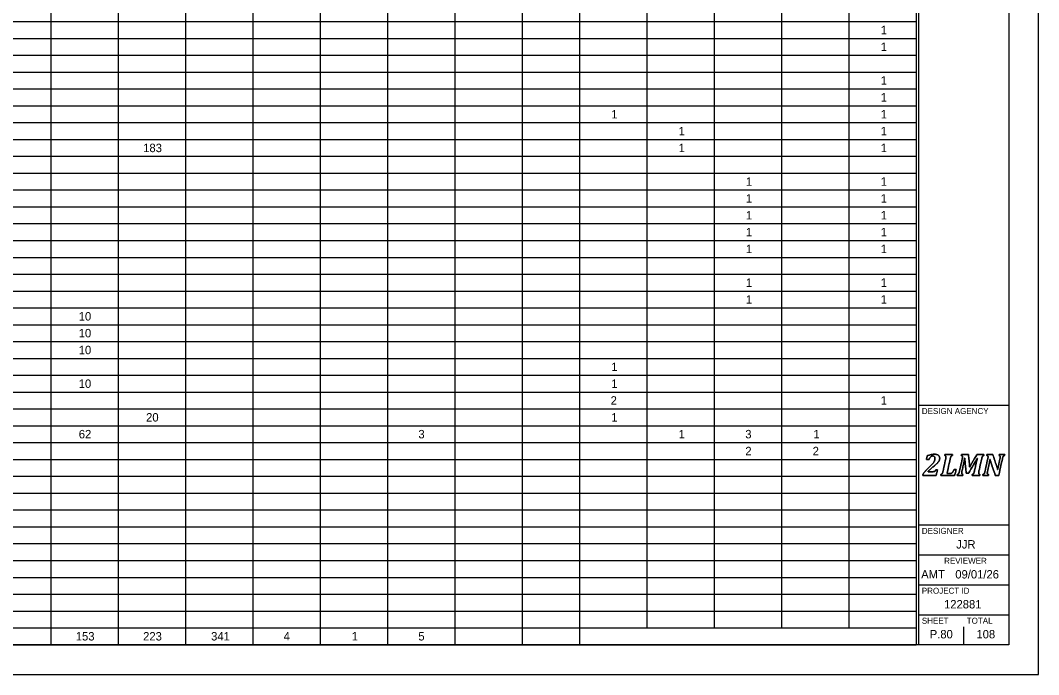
# Model space of a CAD drawing. Extents: x 0 to 34, y 0 to 22.
# Drawn here: x 17 to 34, y 0 to 10.92 of the extents above; entities that cross this region are included whole.
import ezdxf

# ---------------------------------------------------------------- set-up
doc = ezdxf.new("R2010")
doc.units = 0
for name, color, linetype in [('SH_Border', 7, 'Continuous'), ('SH_Cut_Line', 7, 'Continuous'), ('SH_Data', 7, 'Continuous'), ('SH_Text', 7, 'Continuous')]:
    doc.layers.add(name, color=color, linetype=linetype)

msp = doc.modelspace()

# ---------------------------------------------------------------- linework, layer by layer
at = {"layer": 'SH_Border'}
for p, q in [((32, 0.5), (32, 21.5)), ((32, 4.5), (33.5, 4.5)), ((32, 2.5), (33.5, 2.5)), ((32, 2), (33.5, 2)), ((32, 1.5), (33.5, 1.5)), ((32, 1), (33.5, 1))]:
    msp.add_line(p, q, dxfattribs=at)
msp.add_lwpolyline([(1.5, 21.5), (33.5, 21.5), (33.5, 0.5), (1.5, 0.5)], close=True, dxfattribs=at)
at = {"layer": 'SH_Cut_Line'}
msp.add_lwpolyline([(0, 0), (34, 0), (34, 22), (0, 22)], close=True, dxfattribs=at)
at = {"layer": 'SH_Data'}
for p, q in [((32.75, 3.5), (32.75, 3.5)), ((32.75, 0.5), (32.75, 0.8)), ((32.375, 0.675), (32.375, 0.675))]:
    msp.add_line(p, q, dxfattribs=at)
for points in [[(32.237, 3.388), (32.246, 3.388), (32.253, 3.389), (32.258, 3.39), (32.263, 3.392), (32.267, 3.394), (32.27, 3.397), (32.273, 3.401), (32.277, 3.408), (32.281, 3.417), (32.281, 3.417), (32.312, 3.417), (32.312, 3.417), (32.312, 3.417), (32.29, 3.326), (32.29, 3.326), (32.29, 3.326), (32.066, 3.326), (32.066, 3.326), (32.066, 3.326), (32.069, 3.343), (32.069, 3.343), (32.078, 3.358), (32.091, 3.375), (32.106, 3.394), (32.122, 3.412), (32.144, 3.435), (32.172, 3.462), (32.197, 3.486), (32.217, 3.506), (32.23, 3.521), (32.243, 3.537), (32.253, 3.551), (32.259, 3.566), (32.266, 3.58), (32.269, 3.595), (32.269, 3.61), (32.269, 3.622), (32.266, 3.632), (32.26, 3.64), (32.253, 3.647), (32.245, 3.65), (32.234, 3.65), (32.22, 3.65), (32.208, 3.646), (32.198, 3.636), (32.188, 3.627), (32.18, 3.613), (32.172, 3.593), (32.172, 3.593), (32.126, 3.593), (32.126, 3.593), (32.126, 3.593), (32.14, 3.654), (32.14, 3.654), (32.166, 3.663), (32.188, 3.669), (32.205, 3.673), (32.223, 3.676), (32.24, 3.678), (32.258, 3.678), (32.278, 3.678), (32.295, 3.675), (32.309, 3.669), (32.322, 3.664), (32.332, 3.656), (32.339, 3.646), (32.345, 3.637), (32.348, 3.626), (32.348, 3.613), (32.348, 3.602), (32.346, 3.591), (32.342, 3.581), (32.339, 3.571), (32.333, 3.56), (32.324, 3.549), (32.315, 3.539), (32.304, 3.526), (32.289, 3.513), (32.275, 3.499), (32.254, 3.482), (32.228, 3.46), (32.216, 3.45), (32.202, 3.438), (32.188, 3.425), (32.174, 3.412), (32.162, 3.4), (32.154, 3.391), (32.154, 3.391), (32.153, 3.388), (32.153, 3.388), (32.153, 3.388), (32.237, 3.388), (32.237, 3.388)], [(32.237, 3.388), (32.237, 3.388), (32.153, 3.388), (32.153, 3.388), (32.153, 3.388), (32.154, 3.391), (32.154, 3.391), (32.162, 3.4), (32.174, 3.412), (32.188, 3.425), (32.202, 3.438), (32.216, 3.45), (32.228, 3.46), (32.254, 3.482), (32.275, 3.499), (32.289, 3.513), (32.304, 3.526), (32.315, 3.539), (32.324, 3.549), (32.333, 3.56), (32.339, 3.571), (32.342, 3.581), (32.346, 3.591), (32.348, 3.602), (32.348, 3.613), (32.348, 3.626), (32.345, 3.637), (32.339, 3.646), (32.332, 3.656), (32.322, 3.664), (32.309, 3.669), (32.295, 3.675), (32.278, 3.678), (32.258, 3.678), (32.24, 3.678), (32.223, 3.676), (32.205, 3.673), (32.188, 3.669), (32.166, 3.663), (32.14, 3.654), (32.14, 3.654), (32.126, 3.593), (32.126, 3.593), (32.126, 3.593), (32.172, 3.593), (32.172, 3.593), (32.18, 3.613), (32.188, 3.627), (32.198, 3.636), (32.208, 3.646), (32.22, 3.65), (32.234, 3.65), (32.245, 3.65), (32.253, 3.647), (32.26, 3.64), (32.266, 3.632), (32.269, 3.622), (32.269, 3.61), (32.269, 3.595), (32.266, 3.58), (32.259, 3.566), (32.253, 3.551), (32.243, 3.537), (32.23, 3.521), (32.217, 3.506), (32.197, 3.486), (32.172, 3.462), (32.144, 3.435), (32.122, 3.412), (32.106, 3.394), (32.091, 3.375), (32.078, 3.358), (32.069, 3.343), (32.069, 3.343), (32.066, 3.326), (32.066, 3.326), (32.066, 3.326), (32.29, 3.326), (32.29, 3.326), (32.29, 3.326), (32.312, 3.417), (32.312, 3.417), (32.312, 3.417), (32.281, 3.417), (32.281, 3.417), (32.277, 3.408), (32.273, 3.401), (32.27, 3.397), (32.267, 3.394), (32.263, 3.392), (32.258, 3.39), (32.253, 3.389), (32.246, 3.388), (32.237, 3.388)], [(32.518, 3.356), (32.527, 3.356), (32.533, 3.357), (32.538, 3.358), (32.542, 3.36), (32.546, 3.362), (32.55, 3.365), (32.554, 3.368), (32.558, 3.372), (32.562, 3.377), (32.567, 3.382), (32.571, 3.388), (32.576, 3.397), (32.58, 3.405), (32.585, 3.415), (32.589, 3.427), (32.589, 3.427), (32.624, 3.427), (32.624, 3.427), (32.624, 3.427), (32.598, 3.326), (32.598, 3.326), (32.598, 3.326), (32.365, 3.326), (32.365, 3.326), (32.365, 3.326), (32.369, 3.343), (32.369, 3.343), (32.376, 3.345), (32.381, 3.348), (32.385, 3.351), (32.389, 3.355), (32.392, 3.36), (32.395, 3.366), (32.398, 3.373), (32.4, 3.382), (32.403, 3.395), (32.403, 3.395), (32.449, 3.605), (32.449, 3.605), (32.452, 3.615), (32.453, 3.625), (32.453, 3.635), (32.453, 3.642), (32.451, 3.647), (32.448, 3.651), (32.444, 3.654), (32.439, 3.656), (32.432, 3.657), (32.432, 3.657), (32.435, 3.674), (32.435, 3.674), (32.435, 3.674), (32.563, 3.674), (32.563, 3.674), (32.563, 3.674), (32.559, 3.657), (32.559, 3.657), (32.552, 3.655), (32.547, 3.652), (32.543, 3.649), (32.539, 3.645), (32.536, 3.64), (32.533, 3.634), (32.531, 3.627), (32.528, 3.618), (32.525, 3.605), (32.525, 3.605), (32.47, 3.356), (32.47, 3.356), (32.47, 3.356), (32.518, 3.356), (32.518, 3.356)], [(32.518, 3.356), (32.518, 3.356), (32.47, 3.356), (32.47, 3.356), (32.47, 3.356), (32.525, 3.605), (32.525, 3.605), (32.528, 3.618), (32.531, 3.627), (32.533, 3.634), (32.536, 3.64), (32.539, 3.645), (32.543, 3.649), (32.547, 3.652), (32.552, 3.655), (32.559, 3.657), (32.559, 3.657), (32.563, 3.674), (32.563, 3.674), (32.563, 3.674), (32.435, 3.674), (32.435, 3.674), (32.435, 3.674), (32.432, 3.657), (32.432, 3.657), (32.439, 3.656), (32.444, 3.654), (32.448, 3.651), (32.451, 3.647), (32.453, 3.642), (32.453, 3.635), (32.453, 3.625), (32.452, 3.615), (32.449, 3.605), (32.449, 3.605), (32.403, 3.395), (32.403, 3.395), (32.4, 3.382), (32.398, 3.373), (32.395, 3.366), (32.392, 3.36), (32.389, 3.355), (32.385, 3.351), (32.381, 3.348), (32.376, 3.345), (32.369, 3.343), (32.369, 3.343), (32.365, 3.326), (32.365, 3.326), (32.365, 3.326), (32.598, 3.326), (32.598, 3.326), (32.598, 3.326), (32.624, 3.427), (32.624, 3.427), (32.624, 3.427), (32.589, 3.427), (32.589, 3.427), (32.585, 3.415), (32.58, 3.405), (32.576, 3.397), (32.571, 3.388), (32.567, 3.382), (32.562, 3.377), (32.558, 3.372), (32.554, 3.368), (32.55, 3.365), (32.546, 3.362), (32.542, 3.36), (32.538, 3.358), (32.533, 3.357), (32.527, 3.356), (32.518, 3.356)], [(32.829, 3.674), (32.829, 3.674), (32.849, 3.461), (32.849, 3.461), (32.849, 3.461), (32.969, 3.674), (32.969, 3.674), (32.969, 3.674), (33.087, 3.674), (33.087, 3.674), (33.087, 3.674), (33.084, 3.657), (33.084, 3.657), (33.077, 3.655), (33.071, 3.652), (33.067, 3.649), (33.064, 3.645), (33.06, 3.64), (33.058, 3.634), (33.055, 3.627), (33.052, 3.618), (33.05, 3.605), (33.05, 3.605), (33.003, 3.395), (33.003, 3.395), (33.002, 3.39), (33.002, 3.387), (33.001, 3.384), (33.001, 3.382), (33.001, 3.379), (33, 3.376), (33, 3.373), (33, 3.369), (33, 3.365), (33, 3.358), (33.002, 3.353), (33.005, 3.349), (33.008, 3.346), (33.014, 3.344), (33.021, 3.343), (33.021, 3.343), (33.018, 3.326), (33.018, 3.326), (33.018, 3.326), (32.89, 3.326), (32.89, 3.326), (32.89, 3.326), (32.893, 3.343), (32.893, 3.343), (32.9, 3.345), (32.906, 3.348), (32.91, 3.351), (32.914, 3.355), (32.917, 3.36), (32.919, 3.366), (32.922, 3.373), (32.925, 3.382), (32.928, 3.395), (32.928, 3.395), (32.951, 3.502), (32.951, 3.502), (32.954, 3.513), (32.957, 3.529), (32.962, 3.548), (32.967, 3.568), (32.972, 3.588), (32.978, 3.609), (32.978, 3.609), (32.973, 3.609), (32.973, 3.609), (32.965, 3.594), (32.957, 3.579), (32.948, 3.563), (32.948, 3.563), (32.833, 3.364), (32.833, 3.364), (32.833, 3.364), (32.792, 3.364), (32.792, 3.364), (32.792, 3.364), (32.775, 3.518), (32.775, 3.518), (32.773, 3.537), (32.772, 3.554), (32.77, 3.569), (32.769, 3.583), (32.768, 3.597), (32.768, 3.611), (32.768, 3.611), (32.764, 3.611), (32.764, 3.611), (32.761, 3.596), (32.758, 3.578), (32.755, 3.558), (32.751, 3.538), (32.747, 3.521), (32.744, 3.507), (32.744, 3.507), (32.72, 3.395), (32.72, 3.395), (32.719, 3.39), (32.718, 3.387), (32.718, 3.384), (32.717, 3.382), (32.717, 3.379), (32.717, 3.376), (32.717, 3.373), (32.716, 3.369), (32.716, 3.365), (32.716, 3.358), (32.718, 3.353), (32.721, 3.349), (32.725, 3.346), (32.73, 3.344), (32.738, 3.343), (32.738, 3.343), (32.734, 3.326), (32.734, 3.326), (32.734, 3.326), (32.641, 3.326), (32.641, 3.326), (32.641, 3.326), (32.644, 3.343), (32.644, 3.343), (32.651, 3.345), (32.657, 3.348), (32.661, 3.351), (32.665, 3.355), (32.668, 3.36), (32.67, 3.366), (32.673, 3.373), (32.676, 3.382), (32.679, 3.395), (32.679, 3.395), (32.725, 3.605), (32.725, 3.605), (32.727, 3.615), (32.728, 3.625), (32.728, 3.635), (32.728, 3.642), (32.727, 3.647), (32.723, 3.651), (32.72, 3.654), (32.715, 3.656), (32.707, 3.657), (32.707, 3.657), (32.711, 3.674), (32.711, 3.674), (32.711, 3.674), (32.829, 3.674), (32.829, 3.674)], [(32.829, 3.674), (32.829, 3.674), (32.711, 3.674), (32.711, 3.674), (32.711, 3.674), (32.707, 3.657), (32.707, 3.657), (32.715, 3.656), (32.72, 3.654), (32.723, 3.651), (32.727, 3.647), (32.728, 3.642), (32.728, 3.635), (32.728, 3.625), (32.727, 3.615), (32.725, 3.605), (32.725, 3.605), (32.679, 3.395), (32.679, 3.395), (32.676, 3.382), (32.673, 3.373), (32.67, 3.366), (32.668, 3.36), (32.665, 3.355), (32.661, 3.351), (32.657, 3.348), (32.651, 3.345), (32.644, 3.343), (32.644, 3.343), (32.641, 3.326), (32.641, 3.326), (32.641, 3.326), (32.734, 3.326), (32.734, 3.326), (32.734, 3.326), (32.738, 3.343), (32.738, 3.343), (32.73, 3.344), (32.725, 3.346), (32.721, 3.349), (32.718, 3.353), (32.716, 3.358), (32.716, 3.365), (32.716, 3.369), (32.717, 3.373), (32.717, 3.376), (32.717, 3.379), (32.717, 3.382), (32.718, 3.384), (32.718, 3.387), (32.719, 3.39), (32.72, 3.395), (32.72, 3.395), (32.744, 3.507), (32.744, 3.507), (32.747, 3.521), (32.751, 3.538), (32.755, 3.558), (32.758, 3.578), (32.761, 3.596), (32.764, 3.611), (32.764, 3.611), (32.768, 3.611), (32.768, 3.611), (32.768, 3.597), (32.769, 3.583), (32.77, 3.569), (32.772, 3.554), (32.773, 3.537), (32.775, 3.518), (32.775, 3.518), (32.792, 3.364), (32.792, 3.364), (32.792, 3.364), (32.833, 3.364), (32.833, 3.364), (32.833, 3.364), (32.948, 3.563), (32.948, 3.563), (32.957, 3.579), (32.965, 3.594), (32.973, 3.609), (32.973, 3.609), (32.978, 3.609), (32.978, 3.609), (32.972, 3.588), (32.967, 3.568), (32.962, 3.548), (32.957, 3.529), (32.954, 3.513), (32.951, 3.502), (32.951, 3.502), (32.928, 3.395), (32.928, 3.395), (32.925, 3.382), (32.922, 3.373), (32.919, 3.366), (32.917, 3.36), (32.914, 3.355), (32.91, 3.351), (32.906, 3.348), (32.9, 3.345), (32.893, 3.343), (32.893, 3.343), (32.89, 3.326), (32.89, 3.326), (32.89, 3.326), (33.018, 3.326), (33.018, 3.326), (33.018, 3.326), (33.021, 3.343), (33.021, 3.343), (33.014, 3.344), (33.008, 3.346), (33.005, 3.349), (33.002, 3.353), (33, 3.358), (33, 3.365), (33, 3.369), (33, 3.373), (33, 3.376), (33.001, 3.379), (33.001, 3.382), (33.001, 3.384), (33.002, 3.387), (33.002, 3.39), (33.003, 3.395), (33.003, 3.395), (33.05, 3.605), (33.05, 3.605), (33.052, 3.618), (33.055, 3.627), (33.058, 3.634), (33.06, 3.64), (33.064, 3.645), (33.067, 3.649), (33.071, 3.652), (33.077, 3.655), (33.084, 3.657), (33.084, 3.657), (33.087, 3.674), (33.087, 3.674), (33.087, 3.674), (32.969, 3.674), (32.969, 3.674), (32.969, 3.674), (32.849, 3.461), (32.849, 3.461), (32.849, 3.461), (32.829, 3.674), (32.829, 3.674)], [(33.137, 3.674), (33.137, 3.674), (33.234, 3.674), (33.234, 3.674), (33.234, 3.674), (33.283, 3.53), (33.283, 3.53), (33.296, 3.49), (33.307, 3.456), (33.315, 3.426), (33.315, 3.426), (33.318, 3.426), (33.318, 3.426), (33.323, 3.455), (33.329, 3.488), (33.337, 3.523), (33.337, 3.523), (33.355, 3.605), (33.355, 3.605), (33.357, 3.615), (33.358, 3.625), (33.358, 3.635), (33.358, 3.642), (33.357, 3.647), (33.353, 3.651), (33.35, 3.654), (33.345, 3.656), (33.337, 3.657), (33.337, 3.657), (33.341, 3.674), (33.341, 3.674), (33.341, 3.674), (33.434, 3.674), (33.434, 3.674), (33.434, 3.674), (33.431, 3.657), (33.431, 3.657), (33.424, 3.655), (33.418, 3.652), (33.414, 3.649), (33.41, 3.645), (33.407, 3.64), (33.405, 3.634), (33.402, 3.627), (33.399, 3.618), (33.396, 3.605), (33.396, 3.605), (33.335, 3.326), (33.335, 3.326), (33.335, 3.326), (33.277, 3.326), (33.277, 3.326), (33.277, 3.326), (33.216, 3.504), (33.216, 3.504), (33.211, 3.518), (33.207, 3.531), (33.204, 3.543), (33.2, 3.556), (33.195, 3.571), (33.19, 3.59), (33.19, 3.59), (33.186, 3.59), (33.186, 3.59), (33.185, 3.579), (33.182, 3.563), (33.179, 3.543), (33.175, 3.523), (33.17, 3.501), (33.165, 3.478), (33.165, 3.478), (33.147, 3.395), (33.147, 3.395), (33.146, 3.39), (33.145, 3.387), (33.145, 3.384), (33.144, 3.382), (33.144, 3.379), (33.144, 3.376), (33.143, 3.373), (33.143, 3.369), (33.143, 3.365), (33.143, 3.358), (33.145, 3.353), (33.148, 3.349), (33.152, 3.346), (33.157, 3.344), (33.164, 3.343), (33.164, 3.343), (33.161, 3.326), (33.161, 3.326), (33.161, 3.326), (33.067, 3.326), (33.067, 3.326), (33.067, 3.326), (33.071, 3.343), (33.071, 3.343), (33.078, 3.345), (33.083, 3.348), (33.087, 3.351), (33.091, 3.355), (33.094, 3.36), (33.097, 3.366), (33.1, 3.373), (33.102, 3.382), (33.105, 3.395), (33.105, 3.395), (33.151, 3.605), (33.151, 3.605), (33.154, 3.615), (33.155, 3.625), (33.155, 3.635), (33.155, 3.642), (33.153, 3.647), (33.15, 3.651), (33.146, 3.654), (33.141, 3.656), (33.134, 3.657), (33.134, 3.657), (33.137, 3.674), (33.137, 3.674)], [(33.137, 3.674), (33.137, 3.674), (33.134, 3.657), (33.134, 3.657), (33.141, 3.656), (33.146, 3.654), (33.15, 3.651), (33.153, 3.647), (33.155, 3.642), (33.155, 3.635), (33.155, 3.625), (33.154, 3.615), (33.151, 3.605), (33.151, 3.605), (33.105, 3.395), (33.105, 3.395), (33.102, 3.382), (33.1, 3.373), (33.097, 3.366), (33.094, 3.36), (33.091, 3.355), (33.087, 3.351), (33.083, 3.348), (33.078, 3.345), (33.071, 3.343), (33.071, 3.343), (33.067, 3.326), (33.067, 3.326), (33.067, 3.326), (33.161, 3.326), (33.161, 3.326), (33.161, 3.326), (33.164, 3.343), (33.164, 3.343), (33.157, 3.344), (33.152, 3.346), (33.148, 3.349), (33.145, 3.353), (33.143, 3.358), (33.143, 3.365), (33.143, 3.369), (33.143, 3.373), (33.144, 3.376), (33.144, 3.379), (33.144, 3.382), (33.145, 3.384), (33.145, 3.387), (33.146, 3.39), (33.147, 3.395), (33.147, 3.395), (33.165, 3.478), (33.165, 3.478), (33.17, 3.501), (33.175, 3.523), (33.179, 3.543), (33.182, 3.563), (33.185, 3.579), (33.186, 3.59), (33.186, 3.59), (33.19, 3.59), (33.19, 3.59), (33.195, 3.571), (33.2, 3.556), (33.204, 3.543), (33.207, 3.531), (33.211, 3.518), (33.216, 3.504), (33.216, 3.504), (33.277, 3.326), (33.277, 3.326), (33.277, 3.326), (33.335, 3.326), (33.335, 3.326), (33.335, 3.326), (33.396, 3.605), (33.396, 3.605), (33.399, 3.618), (33.402, 3.627), (33.405, 3.634), (33.407, 3.64), (33.41, 3.645), (33.414, 3.649), (33.418, 3.652), (33.424, 3.655), (33.431, 3.657), (33.431, 3.657), (33.434, 3.674), (33.434, 3.674), (33.434, 3.674), (33.341, 3.674), (33.341, 3.674), (33.341, 3.674), (33.337, 3.657), (33.337, 3.657), (33.345, 3.656), (33.35, 3.654), (33.353, 3.651), (33.357, 3.647), (33.358, 3.642), (33.358, 3.635), (33.358, 3.625), (33.357, 3.615), (33.355, 3.605), (33.355, 3.605), (33.337, 3.523), (33.337, 3.523), (33.329, 3.488), (33.323, 3.455), (33.318, 3.426), (33.318, 3.426), (33.315, 3.426), (33.315, 3.426), (33.307, 3.456), (33.296, 3.49), (33.283, 3.53), (33.283, 3.53), (33.234, 3.674), (33.234, 3.674), (33.234, 3.674), (33.137, 3.674), (33.137, 3.674)]]:
    msp.add_open_spline(points, degree=3, dxfattribs=at)
at = {"layer": 'SH_Text'}
for p, q in [((17.506, 21.5), (17.506, 0.5)), ((18.631, 21.5), (18.631, 0.5)), ((19.755, 21.5), (19.755, 0.5)), ((20.88, 21.5), (20.88, 0.5)), ((22.004, 21.5), (22.004, 0.5)), ((23.128, 21.5), (23.128, 0.5)), ((24.253, 21.5), (24.253, 0.5)), ((25.377, 21.5), (25.377, 0.5)), ((26.336, 21.5), (26.336, 0.781)), ((31.958, 21.5), (31.958, 0.5)), ((27.461, 21.219), (27.461, 0.781)), ((28.585, 21.219), (28.585, 0.781)), ((29.709, 21.219), (29.709, 0.781)), ((30.834, 21.219), (30.834, 0.781)), ((1.5, 10.901), (31.958, 10.901)), ((1.5, 10.62), (31.958, 10.62)), ((1.5, 10.339), (31.958, 10.339)), ((1.5, 10.057), (31.958, 10.057)), ((1.5, 9.776), (31.958, 9.776)), ((1.5, 9.495), (31.958, 9.495)), ((1.5, 9.214), (31.958, 9.214)), ((1.5, 8.933), (31.958, 8.933)), ((1.5, 8.652), (31.958, 8.652)), ((1.5, 8.371), (31.958, 8.371)), ((1.5, 8.09), (31.958, 8.09)), ((1.5, 7.809), (31.958, 7.809)), ((1.5, 7.528), (31.958, 7.528)), ((1.5, 7.246), (31.958, 7.246)), ((1.5, 6.965), (31.958, 6.965)), ((1.5, 6.684), (31.958, 6.684)), ((1.5, 6.403), (31.958, 6.403)), ((1.5, 6.122), (31.958, 6.122)), ((1.5, 5.841), (31.958, 5.841)), ((1.5, 5.56), (31.958, 5.56)), ((1.5, 5.279), (31.958, 5.279)), ((1.5, 4.998), (31.958, 4.998)), ((1.5, 4.717), (31.958, 4.717)), ((1.5, 4.435), (31.958, 4.435)), ((1.5, 4.154), (31.958, 4.154)), ((1.5, 3.873), (31.958, 3.873)), ((1.5, 3.592), (31.958, 3.592)), ((1.5, 3.311), (31.958, 3.311)), ((1.5, 3.03), (31.958, 3.03)), ((1.5, 2.749), (31.958, 2.749)), ((1.5, 2.468), (31.958, 2.468)), ((1.5, 2.187), (31.958, 2.187)), ((1.5, 1.906), (31.958, 1.906)), ((1.5, 1.624), (31.958, 1.624)), ((1.5, 1.343), (31.958, 1.343)), ((1.5, 1.062), (31.958, 1.062)), ((1.5, 0.781), (31.958, 0.781)), ((26.336, 0.781), (26.336, 0.5)), ((1.5, 0.5), (31.958, 0.5))]:
    msp.add_line(p, q, dxfattribs=at)

# ---------------------------------------------------------------- texts
at = {"layer": 'SH_Data'}
for s, height, p in [('DESIGN AGENCY', 0.1, (32.05, 4.35)), ('DESIGNER', 0.1, (32.05, 2.35)), ('JJR', 0.14, (32.624, 2.105)), ('REVIEWER', 0.1, (32.422, 1.85)), ('AMT', 0.14, (32.039, 1.605)), ('09/01/26', 0.14, (32.609, 1.605)), ('PROJECT ID', 0.1, (32.05, 1.35)), ('122881', 0.14, (32.421, 1.105)), ('SHEET', 0.1, (32.05, 0.85)), ('TOTAL', 0.1, (32.8, 0.85)), ('P.80', 0.14, (32.182, 0.605)), ('108', 0.14, (32.962, 0.605))]:
    msp.add_text(s, height=height, dxfattribs=at).set_placement(p)
at = {"layer": 'SH_Text'}
for s, height, p in [('1', 0.141, (31.363, 10.69)), ('1', 0.141, (31.363, 10.409)), ('1', 0.141, (31.363, 9.847)), ('1', 0.141, (31.363, 9.566)), ('1', 0.141, (26.866, 9.284)), ('1', 0.141, (31.363, 9.284)), ('1', 0.141, (27.99, 9.003)), ('1', 0.141, (31.363, 9.003)), ('183', 0.1406, (19.05, 8.722)), ('1', 0.141, (27.99, 8.722)), ('1', 0.141, (31.363, 8.722)), ('1', 0.141, (29.114, 8.16)), ('1', 0.141, (31.363, 8.16)), ('1', 0.141, (29.114, 7.879)), ('1', 0.141, (31.363, 7.879)), ('1', 0.141, (29.114, 7.598)), ('1', 0.141, (31.363, 7.598)), ('1', 0.141, (29.114, 7.317)), ('1', 0.141, (31.363, 7.317)), ('1', 0.141, (29.114, 7.036)), ('1', 0.141, (31.363, 7.036)), ('1', 0.141, (29.114, 6.473)), ('1', 0.141, (31.363, 6.473)), ('1', 0.141, (29.114, 6.192)), ('1', 0.141, (31.363, 6.192)), ('10', 0.1406, (17.974, 5.911)), ('10', 0.1406, (17.974, 5.63)), ('10', 0.1406, (17.974, 5.349)), ('1', 0.141, (26.866, 5.068)), ('10', 0.1406, (17.974, 4.787)), ('1', 0.141, (26.866, 4.787)), ('2', 0.141, (26.854, 4.506)), ('1', 0.141, (31.363, 4.506)), ('20', 0.1406, (19.099, 4.225)), ('1', 0.141, (26.866, 4.225)), ('62', 0.1406, (17.975, 3.944)), ('3', 0.141, (23.645, 3.944)), ('1', 0.141, (27.99, 3.944)), ('3', 0.141, (29.102, 3.944)), ('1', 0.141, (30.239, 3.944)), ('2', 0.141, (29.103, 3.662)), ('2', 0.141, (30.227, 3.662)), ('153', 0.1406, (17.925, 0.57)), ('223', 0.1406, (19.049, 0.57)), ('341', 0.1406, (20.184, 0.57)), ('4', 0.141, (21.395, 0.57)), ('1', 0.141, (22.531, 0.57)), ('5', 0.141, (23.644, 0.57))]:
    msp.add_text(s, height=height, dxfattribs=at).set_placement(p)

doc.saveas('drawing.dxf')
